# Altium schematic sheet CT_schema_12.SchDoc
size 144 x 119 mm
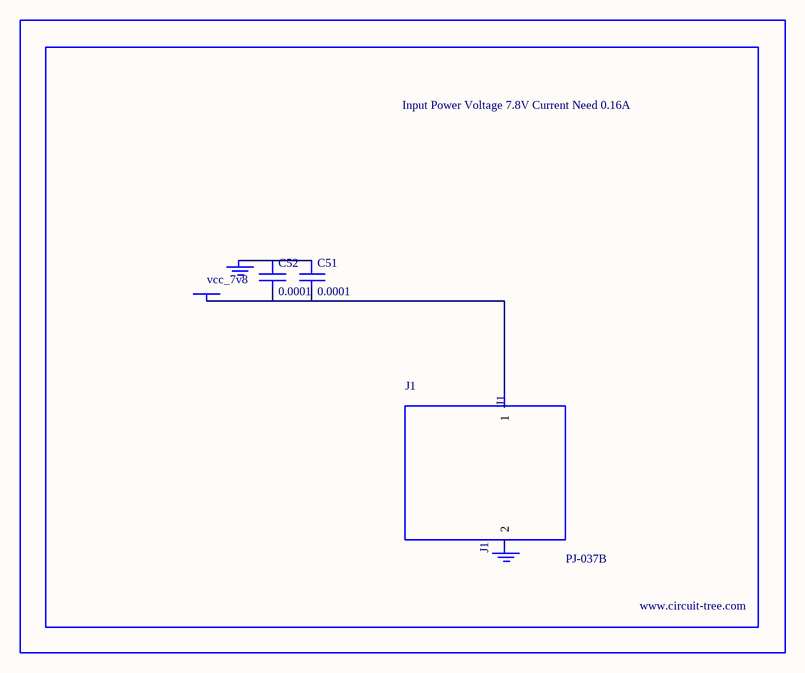
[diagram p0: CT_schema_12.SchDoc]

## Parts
BORDER11  (no value)
C51  0.0001  [EXV-9H]
C52  0.0001  [EXV-9H]
GND_INSTANCE_11_0  (no value)
GND_INSTANCE_11_1  (no value)
J1  PJ-037B  [PJ-037B_PACKAGE]
POWER_INSTANCE_11_0  vcc_7v8

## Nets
NetC51_1: C51.1 C52.1 GND_INSTANCE_11_0.0(GND)
NetC51_2: C51.2 C52.2 J1.1 POWER_INSTANCE_11_0.0(PWR)

Not connected (* = marked no-connect by the designer): GND_INSTANCE_11_1 0(GND); J1 2

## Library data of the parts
BORDER11 = BORDER_PAGE11
C51 C52 = EDK107M035A9HAA
GND_INSTANCE_11_0 GND_INSTANCE_11_1 = GND
POWER_INSTANCE_11_0 = PWR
